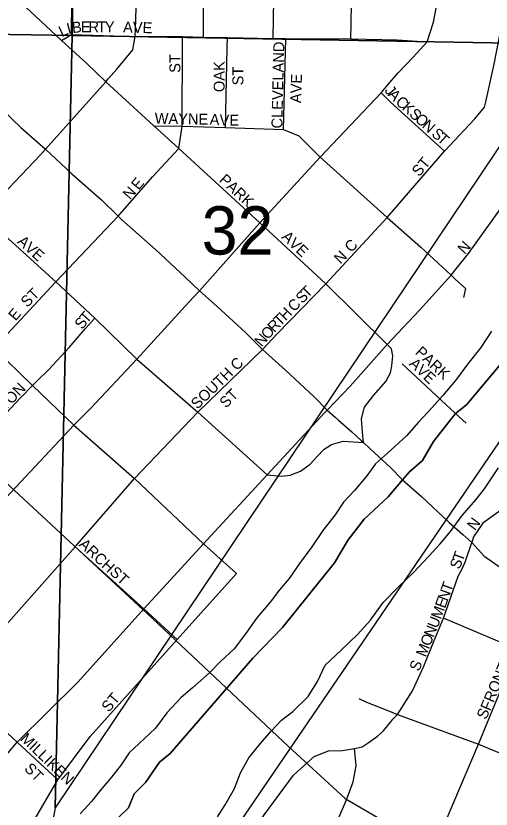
# Model space of a CAD drawing. Extents: x 1310247 to 1552180, y 377264 to 706493.
# Drawn here: x 1383052 to 1385228, y 515640 to 519270 of the extents above; entities that cross this region are included whole.
import ezdxf

# ---------------------------------------------------------------- set-up
doc = ezdxf.new("R2010")
doc.units = 0
for name, color, linetype in [('GM_X_City_Street', 7, 'Continuous'), ('GM_X_City_Street_Text', 7, 'Continuous'), ('GM_X_Major_River', 7, 'Continuous'), ('GM_X_Rail_Line', 7, 'Continuous'), ('GM_X_Section', 7, 'Continuous'), ('GM_X_Section_Text', 7, 'Continuous'), ('GM_X_State_Route', 7, 'Continuous'), ('GM_X_Township', 7, 'Continuous')]:
    doc.layers.add(name, color=color, linetype=linetype)

msp = doc.modelspace()

# ---------------------------------------------------------------- linework, layer by layer
at = {"layer": 'GM_X_City_Street'}
for points in [[(1383306, 519184.8), (1383314.6, 519976.8), (1383332.3, 520640.6), (1383341.7, 521190.1), (1383347.1, 521563.6), (1383342.3, 521916.7), (1383358, 522559.7)], [(1383910.2, 519172.7), (1383912.8, 519970.6), (1383923.6, 520622.4), (1383932.9, 521178), (1383939.2, 521557.3), (1383944.9, 521898), (1383945.1, 521910.3)], [(1383599, 519208.9), (1383602.1, 519305.6), (1383617.2, 519974.6), (1383646.6, 520635.2), (1383646.4, 520663.8)], [(1384229.9, 519166.8), (1384233.2, 519347), (1384245.5, 519963.9), (1384249.2, 520612.8)], [(1385073.5, 518120.3), (1385123.6, 518183.4), (1385472.4, 518668.5), (1386225.3, 519813.4), (1386439.5, 520177.3), (1386453.3, 520200.9)], [(1384585.6, 519165.1), (1384586.7, 519232.9), (1384597.8, 519911.1), (1384598.6, 519958.3), (1384598.7, 519963.5)], [(1382060.1, 516033.9), (1382104.8, 516087.7), (1382315, 516321.7), (1382476.1, 516500), (1383317.1, 517397.1), (1383393, 517472.9), (1383606.1, 517698.8), (1383843.4, 517960.5), (1383892.2, 518012.4), (1384168.5, 518323.6), (1384445.5, 518623.4), (1384723.7, 518917.2), (1384754.5, 518954.7), (1384802.6, 519010.1), (1384870.3, 519081.1), (1384934.9, 519151), (1384963.2, 519241.2), (1384975.5, 519304.9), (1385003.5, 519439.2), (1385040.1, 519628), (1385030.1, 519668.9), (1385010.2, 519743.5), (1384968.2, 519815.7), (1384966.2, 519820.9)], [(1385203.2, 518876), (1385242.3, 519048.5), (1385369.1, 519710.5), (1385362.3, 519777.8), (1385349.3, 519797.7), (1385326, 519814.9), (1385307.4, 519820.1), (1385244.5, 519818.8)], [(1384751.5, 517766.8), (1384470.2, 518043.9), (1384168.5, 518323.6), (1383963.8, 518511), (1383798.2, 518663.8), (1383682.7, 518766.6), (1383464, 518968.7), (1383374.4, 519053.2), (1383261.4, 519157), (1383000.6, 519401.5), (1382701.5, 519665)], [(1381969.3, 519208), (1382117.2, 519074.1), (1382899.1, 518356.7), (1383235.2, 518052.6), (1383413.6, 517887.1), (1383606.1, 517698.8), (1383885.3, 517456), (1384202.2, 517170.1), (1384268.7, 517164.4), (1384309.3, 517168.7), (1384315.3, 517171)], [(1383474.8, 518981.4), (1383513.4, 519026.8), (1383587.6, 519115.3), (1383597.9, 519175.3), (1383599, 519208.9)], [(1383261.4, 519157), (1383306, 519184.8), (1383597.9, 519175.3), (1383815.2, 519175.4), (1383910.2, 519172.7), (1384021.3, 519171.4), (1384229.9, 519166.8), (1384287.6, 519166.1), (1384585.6, 519165.1), (1384798.2, 519160.7), (1384934.9, 519151)], [(1383813.8, 518768.5), (1383813.2, 518818.1), (1383815.2, 519094.5), (1383815.2, 519175.4)], [(1384011.2, 518759.3), (1384018.6, 519123.6), (1384021.3, 519171.4)], [(1384276.9, 518749.8), (1384287.6, 519166.1)], [(1383187.5, 518659.6), (1383464, 518968.7), (1383474.8, 518981.4)], [(1384723.7, 518917.2), (1384765, 518876.7), (1385014.4, 518651.5)], [(1384470.2, 518043.9), (1384489.5, 518064.3), (1384751.2, 518347.7), (1385014.4, 518651.5), (1385153.4, 518798.2), (1385197.8, 518852.2), (1385203.2, 518876)], [(1383519.5, 518353.3), (1383677.4, 518533.1), (1383798.2, 518663.8), (1383813.9, 518765.2), (1383813.8, 518768.5)], [(1383682.7, 518766.6), (1383813.9, 518765.2), (1384011.2, 518759.3), (1384276.9, 518749.8), (1384347.2, 518721.8), (1384445.5, 518623.4), (1384751.2, 518347.7), (1384905.2, 518211.2), (1385044, 518083.1), (1385063.6, 518065.2)], [(1382810.4, 518267.3), (1382899.1, 518356.7), (1383164.6, 518633.9), (1383187.5, 518659.6)], [(1382228.5, 518422.2), (1382245.7, 518406.7), (1382614.3, 518052.3), (1382950.7, 517750), (1383127.5, 517579.2), (1383317.1, 517397.1), (1383595.4, 517153.9), (1383910.9, 516854.2), (1384062, 516718.5)], [(1382712, 517495.9), (1382950.7, 517750), (1383235.2, 518052.6), (1383519.5, 518353.3)], [(1383926.8, 516871.5), (1384202.2, 517170.1), (1384465, 517453.7), (1384477.5, 517465.7), (1384581.6, 517575.6), (1384751.5, 517766.8), (1384899, 517923.2), (1385044, 518083.1), (1385060.9, 518104.4), (1385073.5, 518120.3)], [(1384181.6, 517742.9), (1384247.8, 517815.8), (1384470.2, 518043.9)], [(1385063.6, 518065.2), (1385110, 518023.2), (1385101.3, 517980.7)], [(1383145.5, 517596.8), (1383202.2, 517652.2), (1383295.4, 517752.2), (1383368.4, 517837.8), (1383413.6, 517887.1)], [(1384643.5, 517317.4), (1384638.3, 517366.8), (1384634, 517426.6), (1384647.3, 517479), (1384689.5, 517532.9), (1384745.6, 517596.5), (1384767.5, 517636), (1384773.4, 517669.1), (1384778.2, 517714), (1384772.3, 517746), (1384751.5, 517766.8)], [(1383885.3, 517456), (1384181.6, 517742.9)], [(1384820.8, 517677.9), (1385064.4, 517451.1), (1385112.9, 517405.9)], [(1383076.6, 517526), (1383127.5, 517579.2), (1383145.5, 517596.8)], [(1382873, 517310.5), (1383072.9, 517522.1), (1383076.6, 517526)], [(1382755.5, 516201.5), (1382771.3, 516218.3), (1383322.9, 516840.8), (1383595.4, 517153.9), (1383885.3, 517456)], [(1384315.3, 517171), (1384355.2, 517186.3), (1384398.5, 517218.4), (1384429.4, 517253.1), (1384462.6, 517286.7), (1384497.3, 517308.6), (1384550.7, 517324.1), (1384643.5, 517317.4)], [(1383058.3, 515946.3), (1382882.1, 516108.7), (1382771.3, 516218.3), (1382476.1, 516500), (1382089, 516833.2), (1381775.5, 517126.4)], [(1385338.4, 517036), (1385270, 517006.6), (1385189.7, 516949), (1385147.3, 516887), (1385139.8, 516860.4)], [(1382950.9, 515821.3), (1383058.3, 515946.3), (1383336.6, 516222.7), (1383637.5, 516556.2), (1383690.8, 516615.3), (1383910.9, 516854.2), (1383926.8, 516871.5)], [(1383322.9, 516840.8), (1383637.5, 516556.2), (1383790.8, 516416.9)], [(1385009.1, 516514.6), (1385077.5, 516705.8), (1385090.7, 516731.2), (1385109.4, 516771), (1385139.8, 516860.4)], [(1382870, 514676.3), (1382968, 515238.5), (1383043.1, 515429.6), (1383243.8, 515773.8), (1383391.6, 515972.8), (1383790.8, 516416.9), (1384062, 516718.5)], [(1384798.4, 516073.9), (1384868.1, 516181.8), (1384920.3, 516293.8), (1384964.6, 516404.2), (1385009.1, 516514.6)], [(1386651.9, 515845.2), (1386465.5, 515926.3), (1386224.4, 516026.6), (1386001.4, 516120.1), (1385775.8, 516209), (1385349.1, 516370.1), (1385009.1, 516514.6)], [(1384963.1, 515450.4), (1384974.6, 515479), (1385169.6, 515938.4), (1385349.1, 516370.1)], [(1384621.4, 516146.4), (1384656.6, 516129.8), (1384746.4, 516095), (1384798.4, 516073.9)], [(1384602.3, 515918.1), (1384637.2, 515925.6), (1384665.3, 515943), (1384707.8, 515974.1), (1384732.8, 515997.8), (1384768.4, 516039.7), (1384778.2, 516051.3), (1384790.1, 516064.6), (1384798.4, 516073.9)], [(1384798.4, 516073.9), (1385169.6, 515938.4), (1385599, 515760.9), (1386029.5, 515581.1), (1386067.9, 515565.1)], [(1383058.3, 515946.3), (1383243.8, 515773.8)], [(1383544.9, 512028.4), (1383528.1, 512467.2), (1383538.1, 512962.2), (1383541.5, 513128.7), (1383585.8, 513807.1), (1383612.4, 514191.3), (1383622.2, 514257.8), (1383659.4, 514499.4), (1383709.8, 514694.7), (1383766.3, 514881), (1383838, 515072.1), (1383932.4, 515262.1), (1384077.6, 515462.9), (1384095.8, 515487.8), (1384323.6, 515795.4), (1384416.9, 515881.5), (1384483.4, 515906.8), (1384546.9, 515909), (1384602.3, 515918.1)], [(1384509.9, 515558), (1384522.5, 515584.3), (1384564.9, 515682.2), (1384596, 515765.2), (1384610.1, 515838.2), (1384602.3, 515918.1)]]:
    msp.add_lwpolyline(points, dxfattribs=at)
at = {"layer": 'GM_X_Major_River'}
for points in [[(1385229.3, 517827.2), (1385180.9, 517752.5), (1385120.5, 517678.2), (1385064.1, 517601.8), (1385005.9, 517533.4), (1384958.1, 517478.8), (1384895.9, 517410.5), (1384839.9, 517348.1), (1384753.3, 517268.6), (1384697.7, 517220.2), (1384658, 517165.3), (1384601.9, 517098.9), (1384552.1, 517044.3), (1384514.3, 516987.4), (1384457.9, 516914.9), (1384407.5, 516840.3), (1384351.1, 516763.9), (1384302.9, 516695.2), (1384259.3, 516644.5), (1384215.4, 516587.7), (1384155.1, 516515.4), (1384102.8, 516442.8), (1384050.6, 516374.3), (1383988.7, 516316.1), (1383939, 516263.5), (1383860.8, 516195.8), (1383809.3, 516151.2), (1383743.1, 516081.1), (1383690.8, 516010.6), (1383639.2, 515962.1), (1383571.2, 515898), (1383533.4, 515843.1), (1383489.6, 515786.3), (1383437.6, 515725.8), (1383398, 515674.9), (1383346.2, 515618.3)], [(1383974.4, 515604.9), (1384010.1, 515659.9), (1384052.5, 515734.7), (1384080.8, 515806), (1384119, 515875), (1384162.7, 515929.8), (1384218.9, 515996.2), (1384268.5, 516046.8), (1384319.8, 516087.3), (1384390, 516155.3), (1384432.2, 516224.1), (1384468.6, 516299.2), (1384540.8, 516367.1), (1384615.2, 516439), (1384675.3, 516505.3), (1384733.9, 516585.6), (1384804.2, 516657.6), (1384872.3, 516723.7), (1384942.7, 516797.7), (1384994.6, 516854.2), (1385042.4, 516910.8), (1385094.7, 516983.4), (1385157, 517055.6), (1385196.7, 517106.5), (1385261.8, 517202.7)]]:
    msp.add_lwpolyline(points, dxfattribs=at)
at = {"layer": 'GM_X_Rail_Line'}
for points in [[(1380523.1, 519281.4), (1380732.1, 519144.4), (1380824.3, 519084.5), (1380947.7, 518994.1), (1381048.3, 518916.2), (1381178.9, 518810.2), (1381449.6, 518571.8), (1381946.7, 518111.9), (1382452.1, 517647.1), (1383636.1, 516551.2)], [(1383636.1, 516551.2), (1383652.3, 516536.2)], [(1383652.3, 516536.2), (1384300.3, 515927.7), (1384558.7, 515689.1), (1384889.1, 515497), (1385209.1, 515379), (1385422.6, 515288.7)]]:
    msp.add_lwpolyline(points, dxfattribs=at)
at = {"layer": 'GM_X_Section'}
for points in [[(1378082.1, 524540.1), (1383388.5, 524456.9), (1383309.9, 519180.3), (1377993.5, 519265.8), (1378074, 524276.3)], [(1383388.5, 524456.9), (1388864, 524337.7), (1385581.1, 519140.4), (1383309.9, 519180.3)], [(1388967.2, 519839.1), (1388423.3, 514157.2), (1383450.7, 514662.8), (1387101, 520009.7)], [(1383309.9, 519180.3), (1383231.1, 515645.8), (1382846.4, 513604.5), (1377881.8, 513677.9), (1377885.2, 513737.8), (1377986.5, 518961.9), (1377993.5, 519265.8)], [(1383309.9, 519180.3), (1385581.1, 519140.4), (1383231.1, 515645.8)]]:
    msp.add_lwpolyline(points, close=True, dxfattribs=at)
at = {"layer": 'GM_X_State_Route'}
for points in [[(1382589.3, 519200.1), (1382686.2, 519115.5), (1382782, 519032.9), (1382950.7, 518876.3), (1383075.1, 518759.9), (1383187.5, 518659.6), (1383308, 518547.1), (1383443.2, 518428), (1383519.5, 518353.3), (1383535.7, 518338.8)], [(1383535.7, 518338.8), (1383690.7, 518200.5), (1383826.4, 518075.1), (1383892.2, 518012.4), (1383973.2, 517939.5), (1384103.2, 517820.7), (1384181.6, 517742.9), (1384286.7, 517649.4), (1384417.2, 517527.1), (1384477.5, 517465.7), (1384514.2, 517433.9)], [(1384514.2, 517433.9), (1384529.3, 517420.7), (1384589.5, 517366.2), (1384633, 517326.8)], [(1384633, 517326.8), (1384643.5, 517317.4), (1384672.3, 517290.7)], [(1384672.3, 517290.7), (1384766.9, 517203.4), (1384822, 517146.5), (1384908.3, 517071.1), (1385035.6, 516952.6), (1385098.9, 516897.6), (1385139.8, 516860.4), (1385198, 516796.1), (1385218, 516782.4)], [(1385218, 516782.4), (1385265.8, 516749.7), (1385316.2, 516714.3), (1385384.3, 516688.7), (1385470.7, 516658.2), (1385543.5, 516624.6), (1385696.7, 516561), (1385897.9, 516481)]]:
    msp.add_lwpolyline(points, dxfattribs=at)
at = {"layer": 'GM_X_Township'}
for points in [[(1385384.9, 517811.5), (1385114.5, 517490), (1385064.4, 517451.1), (1384963.7, 517322.2), (1384913.6, 517235.5), (1384853.8, 517183.6), (1384822, 517146.5), (1384756.3, 517069.9), (1384646.7, 516966.7), (1384573.5, 516872.5), (1384511.2, 516766.7), (1384272.3, 516471), (1384136.6, 516331.5), (1383757.9, 515895.2), (1383709.5, 515855.8), (1383646, 515762.1), (1383594.1, 515709.9), (1383568, 515646), (1383479.9, 515562.2)], [(1383479.9, 515562.2), (1383568, 515646), (1383594.1, 515709.9), (1383646, 515762.1), (1383709.5, 515855.8), (1383757.9, 515895.2), (1384136.6, 516331.5), (1384272.3, 516471), (1384511.2, 516766.7), (1384573.5, 516872.5), (1384646.7, 516966.7), (1384756.3, 517069.9), (1384822, 517146.5), (1384853.8, 517183.6), (1384913.6, 517235.5), (1384963.7, 517322.2), (1385064.4, 517451.1), (1385114.5, 517490), (1385384.9, 517811.5)]]:
    msp.add_lwpolyline(points, dxfattribs=at)

# ---------------------------------------------------------------- texts
at = {"layer": 'GM_X_City_Street_Text'}
for s, rotation, p in [('I', 14.5288, (1383291.6, 519186.2)), ('B', 4.8429, (1383310.7, 519191.4)), ('E', 0, (1383349.1, 519194.7)), ('R', 0, (1383384.3, 519194.7)), ('T', 0, (1383423.9, 519194.7)), ('Y', 0, (1383459.1, 519194.7)), ('AVE', 358.0261, (1383541.9, 519194.7)), ('L', 24.2147, (1383261.6, 519172.5)), ('CLEVELAND', 88.6204, (1384271.4, 518754.3)), ('ST', 90, (1383805, 519009.3)), ('OAK', 90, (1384007.4, 518921.3)), ('ST', 90, (1384093.4, 518952.1)), ('AVE', 88.0264, (1384357.4, 518870.2)), ('J', 309.0217, (1384737, 518927.1)), ('A', 312.0535, (1384752.7, 518907.8)), ('C', 318.1619, (1384786.3, 518871)), ('K', 318.437, (1384816, 518844.4)), ('S', 318.4209, (1384848.9, 518815.3)), ('WAYNE', 358.8989, (1383687, 518776.7)), ('A', 356.7195, (1383938.2, 518772.3)), ('V', 357.8367, (1383983.2, 518769.7)), ('E', 359.8007, (1384029, 518768)), ('O', 318.4291, (1384875.3, 518791.9)), ('N', 318.4291, (1384908.2, 518762.7)), ('S', 318.4328, (1384951, 518724.7)), ('T', 318.4209, (1384977.3, 518701.4)), ('ST', 50.1962, (1384898.4, 518531.3)), ('PARK', 317.2013, (1383979.2, 518514.6)), ('E', 50.2016, (1383613.6, 518469.7)), ('N', 48.8121, (1383574.1, 518425.9)), ('AVE', 317.8665, (1383055.1, 518233)), ('AVE', 316.3964, (1384265.3, 518254.9)), ('C', 45, (1384586.6, 518184.3)), ('N', 48.2013, (1385106.3, 518176)), ('N', 45, (1384538.2, 518131.5)), ('T', 45.6954, (1384387.8, 517976.1)), ('ST', 44.995, (1383103.8, 517933.5)), ('S', 45.7042, (1384363.3, 517950.9)), ('C', 45.687, (1384326.4, 517913.1)), ('E', 49.4006, (1383050.5, 517871.4)), ('H', 45.6955, (1384286.4, 517872.1)), ('S', 52.9444, (1383355.9, 517832.2)), ('T', 48.2564, (1383376.4, 517859.5)), ('T', 45.734, (1384261.9, 517846.9)), ('R', 46.5542, (1384234.8, 517818.3)), ('N', 48.7585, (1384176.9, 517752.7)), ('O', 48.4872, (1384205.9, 517785.7)), ('PARK', 317.2013, (1384876.6, 517726.1)), ('SOUTH C', 44.325, (1383882.6, 517467.2)), ('AVE', 316.3964, (1384848.7, 517674.2)), ('HUESTON', 46.2435, (1382874.8, 517326.2)), ('ST', 45.005, (1384013.8, 517472.3)), ('N', 53.1257, (1385153.3, 516911.7)), ('ARCH', 317.1199, (1383336.8, 516847)), ('T', 70.0497, (1385096.8, 516769.2)), ('S', 66.9324, (1385081.9, 516734.1)), ('ST', 317.4834, (1383477.6, 516719.4)), ('T', 70.0134, (1385043.3, 516630.2)), ('N', 70.0272, (1385028.2, 516588.9)), ('E', 70.0134, (1385016.2, 516555.8)), ('M', 69.3993, (1384997.4, 516505.8)), ('U', 68.0361, (1384980.5, 516463.8)), ('N', 67.9753, (1384964, 516422.9)), ('O', 67.9753, (1384947.5, 516382.1)), ('M', 67.977, (1384927.7, 516333.2)), ('S', 66.7995, (1384896.9, 516267.4)), ('FRONT', 67.2856, (1385222.5, 516086.9)), ('ST', 50.1962, (1383477.2, 516080.5)), ('S', 66.7995, (1385205, 516047.4)), ('MILLIKEN', 316.2182, (1383068.5, 515958.1)), ('ST', 315.005, (1383087, 515822.3))]:
    msp.add_text(s, height=50, rotation=rotation, dxfattribs=at).set_placement(p)
at = {"layer": 'GM_X_Section_Text'}
msp.add_text('32', height=221, rotation=0, dxfattribs=at).set_placement((1383902.4, 518178))

doc.saveas('drawing.dxf')
